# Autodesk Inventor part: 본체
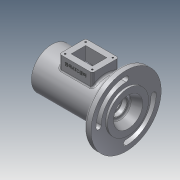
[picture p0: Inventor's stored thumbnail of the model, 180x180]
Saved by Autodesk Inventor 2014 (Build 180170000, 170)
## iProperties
Created: 2017-05
Part Number: 본체
Material: 알루미늄 6061
Document SubType Name: Modeling
Designer: user
Density: 2.71 g/cm^3
Appearance: 알루미늄 - 평지
Mass: 679.751 g
Surface Area: 618.465 cm^2
Volume: 250.831 cm^3
Author: user
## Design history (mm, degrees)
sketch "스케치1"
  geometry: L1 (-57.5, 0)-(57.5, 0); L2 (-57.5, 0)-(-57.5, 31); L3 (-57.5, 31)-(44.5, 31); L4 (44.5, 31)-(44.5, 53); L5 (44.5, 53)-(54.5, 53); L6 (54.5, 53)-(54.5, 31); L7 (54.5, 31)-(57.5, 31); L8 (57.5, 31)-(57.5, 0); 2 further points
  constraints: 16 end point, 3 parallel, 3 perpendicular, 1 coincident, 1 collinear, 1 horizontal, 1 midpoint
  dimensions: "d0" = 115 distance of L1.start L1.end; "d1" = 62 diameter of L3 L1; "d2" = 106 diameter of L5 L1; "d3" = 62 diameter of L7 L1; "d4" = 3 distance of L6.end L7.end; "d5" = 13 distance between parallel lines of L4 L8
revolve "회전1" sketch "스케치1" stored, may be unused: angle "d6" = 90 deg
sketch "스케치2"
  geometry: L1 (-57.5, -31)-(-57.5, 31) reference; L2 (-57.5, 31)-(44.5, 31) reference; L3 (44.5, 31)-(44.5, 53) reference; L4 (44.5, 53)-(54.5, 53) reference; L5 (54.5, 53)-(54.5, 31) reference; L6 (54.5, 31)-(57.5, 31) reference; L7 (57.5, 31)-(57.5, -31) reference; L8 (57.5, -31)-(54.5, -31) reference; L9 (54.5, -31)-(54.5, -53) reference; L10 (54.5, -53)-(44.5, -53) reference; L11 (44.5, -53)-(44.5, -31) reference; L12 (44.5, -31)-(-57.5, -31) reference; L13 (-57.5, 0)-(-48.5, 0); L14 (-48.5, 0)-(-48.5, 21); L15 (-48.5, 21)-(-57.5, 21); L16 (-57.5, 21)-(-57.5, 0); L17 (-48.5, 0)-(-45.5, 0); L18 (-45.5, 0)-(-45.5, 24); L19 (-45.5, 24)-(-48.5, 24); L20 (-48.5, 24)-(-48.5, 0); L21 (-45.5, 0)-(-36.5, 0); L22 (-36.5, 0)-(-36.5, 20); L23 (-36.5, 20)-(-45.5, 20); L24 (-45.5, 20)-(-45.5, 0); L25 (-36.5, 0)-(-33.25, 0); L26 (-33.25, 0)-(-33.25, 17.5); L27 (-33.25, 17.5)-(-36.5, 17.5); L28 (-36.5, 17.5)-(-36.5, 0); L29 (-33.25, 0)-(-31.5, 0); L30 (-31.5, 0)-(-31.5, 18.5); L31 (-31.5, 18.5)-(-33.25, 18.5); L32 (-33.25, 18.5)-(-33.25, 0); L33 (-31.5, 0)-(-20.5, 0); L34 (-20.5, 0)-(-20.5, 17.5); L35 (-20.5, 17.5)-(-31.5, 17.5); L36 (-31.5, 17.5)-(-31.5, 0); L37 (-20.5, 0)-(17.5, 0); L38 (17.5, 0)-(17.5, 26); L39 (17.5, 26)-(-20.5, 26); L40 (-20.5, 26)-(-20.5, 0); L41 (17.5, 0)-(28.5, 0); L42 (28.5, 0)-(28.5, 17.5); L43 (28.5, 17.5)-(17.5, 17.5); L44 (17.5, 17.5)-(17.5, 0); L45 (28.5, 0)-(33.5, 0); L46 (33.5, 0)-(33.5, 13.5); L47 (30.5, 16.5)-(28.5, 16.5); L48 (28.5, 16.5)-(28.5, 0); L49 (33.5, 0)-(36.2, 0); L50 (36.2, 0)-(36.2, 10); L51 (36.2, 10)-(33.5, 10); L52 (33.5, 10)-(33.5, 0); L53 (36.2, 0)-(43.5, 0); L54 (43.5, 0)-(43.5, 12.5); L55 (43.5, 12.5)-(36.2, 12.5); L56 (36.2, 12.5)-(36.2, 0); L57 (43.5, 0)-(43.5, 16); L58 (43.5, 16)-(57.5, 22); L59 (57.5, 0)-(43.5, 0); L60 (57.5, 22)-(57.5, 0); A1 r 3 centre (30.5, 13.5) between (33.5, 13.5) and (30.5, 16.5); 1 further point
  constraints: 96 end point, 23 parallel, 11 horizontal, 11 perpendicular, 4 collinear, 2 midpoint, 2 point on circle, 2 tangent, 1 centre point, 1 point on line
  dimensions: "d7" = 44 diameter of L58.end L59; "d8" = 32 diameter of L57.end L59; "d9" = 25 diameter of L55 L59; "d10" = 20 diameter of L51 L59; "d11" = 33 diameter of L47 L59; "d12" = 35 diameter of L43 L59; "d13" = 52 diameter of L39 L59; "d14" = 37 diameter of L31 L59; "d15" = 40 diameter of L23 L59; "d16" = 48 diameter of L19 L59; "d17" = 42 diameter of L15 L59; "d18" = 12 distance between parallel lines of L24 L1; "d19" = 3 distance of L18.end L19.end; "d20" = 21 distance between parallel lines of L22 L16; "d21" = 26 distance between parallel lines of L30 L1; "d22" = 1.75 distance of L30.end L31.end; "d23" = 60 distance between parallel lines of L42 L30; "d24" = 14 distance between parallel lines of L57 L60; "d25" = 24 distance between parallel lines of L46 L7; "d26" = 38 distance of L38.end L39.end; "d27" = 11 distance of L42.end L43.end; "d28" = 7.3 distance of L54.end L55.end; "d29" = 3 radius of A1
revolve "회전2" sketch "스케치2" stored, may be unused: angle "d30" = 90 deg
node "작업 평면1"
sketch "스케치3"
  geometry: L1 (26.5, -20)-(-23.5, -20); L2 (-23.5, -20)-(-23.5, 20); L3 (-23.5, 20)-(26.5, 20); L4 (26.5, 20)-(26.5, -20); L5 (1.5, -20)-(1.5, 20); L6 (57.5, 31)-(57.5, -31) reference; L7 (-14.5, -11)-(17.5, -11); L8 (17.5, -11)-(17.5, 11); L9 (17.5, 11)-(-14.5, 11); L10 (-14.5, 11)-(-14.5, -11); 2 further points
  constraints: 18 end point, 4 parallel, 3 midpoint, 2 perpendicular, 1 horizontal, 1 horizontal alignment, 3 other
  dimensions: "d32" = 50 distance of L2.end L3.end; "d33" = 40 distance of L3.end L1.start; "d34" = 31 distance between parallel lines of L6 L4; "d35" = 22 distance of L7.end L8.end
extrude "돌출1" join sketch "스케치3" stored distance "d36" = 10; taper "d37" = 0 deg
sketch "스케치5"
  geometry: L1 (-26.5, 20)-(23.5, 20) reference; L2 (-26.5, -20)-(-26.5, 20) reference; L3 (23.5, -20)-(-26.5, -20) reference; L4 (23.5, 20)-(23.5, -20) reference; L5 (19, 15.5)-(-22, 15.5); L6 (-22, 15.5)-(-22, -15.5); L7 (-22, -15.5)-(19, -15.5); L8 (19, -15.5)-(19, 15.5); 1 further point
  constraints: 8 end point, 3 other
  dimensions: "d38" = 31 distance of L5.end L6.end
hole "구멍1" sketch "스케치5" at (-22, -15.5), (-22, 15.5), (19, 15.5), (19, -15.5) diameter "d39" = 2.459; stored, may be unused: countersink angle "d43" = 90 deg, drill point angle "d45" = 118 deg; dims "d40" = 6, "d41" = 4, "d42" = 2, "d44" = 8
sketch "스케치6"
  geometry: C1 r 53 at (0, 0) reference; A1 r 41.5 centre (0, 0) between (0, -41.5) and (41.5, 0); A2 r 45.5 centre (0, 0) between (0, -45.5) and (45.5, 0); A3 r 37.5 centre (0, 0) between (0, -37.5) and (37.5, 0); A4 r 4 centre (0, -41.5) between (0, -37.5) and (0, -45.5); A5 r 4 centre (41.5, 0) between (45.5, 0) and (37.5, 0); A6 r 41.5 centre (0, 0) between (0, 41.5) and (-41.5, 0); A7 r 45.5 centre (0, 0) between (0, 45.5) and (-45.5, 0); A8 r 37.5 centre (0, 0) between (0, 37.5) and (-37.5, 0); A9 r 4 centre (0, 41.5) between (0, 37.5) and (0, 45.5); A10 r 4 centre (-41.5, 0) between (-45.5, 0) and (-37.5, 0)
  constraints: 20 point on circle, 10 centre point, 8 tangent, 2 coincident, 2 horizontal alignment, 2 vertical alignment
  dimensions: "d46" = 41.5 radius of A1; "d47" = 8 diameter of A5; "d48" = 41.5 radius of A6; "d49" = 8 diameter of A9
extrude "돌출2" cut sketch "스케치6" stored distance "d50" = 10; taper "d51" = 0 deg
feature "스레드1" dims "d52" = 10, "d53" = 0
fillet "모깎기1" dims "d54" = 0.3
fillet "모깎기2" dims "d55" = 0.3
chamfer "모따기1" distance "d56" = 0.7; stored, may be unused: second distance "d57" = 2, angle "d58" = 30 deg
fillet "모깎기3" dims "d59" = 3
fillet "모깎기4" dims "d60" = 3
fillet "모깎기5" dims "d61" = 3
fillet "모깎기6" dims "d62" = 3
extrude "돌출3" cut sketch "스케치3" stored distance "d63" = 10; taper "d64" = 0 deg
sketch "스케치7"
  geometry: L1 (44, 0)-(0, 0) reference; L2 (-34, -75)-(-34, -13) reference; 2 further points
  constraints: 1 other
  dimensions: "d65" = 8 distance from line of L1 point (22, -8); "d66" = 56 distance from line of point (22, -8) L2
feature "엠보싱1" sketch "스케치7" dims "d0" = 115, "d1" = 62, "d2" = 106, "d3" = 62, "d4" = 3, "d5" = 13, "d67" = 0.5, "d68" = 0
chamfer "모따기2" distance "d69" = 1; stored, may be unused: second distance "d70" = 2, angle "d71" = 30 deg
node "솔리드1"
node "절단 모서리 투영1"
other parameters: "d31" = 44
